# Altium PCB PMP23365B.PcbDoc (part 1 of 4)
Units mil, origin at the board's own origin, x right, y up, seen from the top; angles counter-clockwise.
Board outline 5450 x 2600 mil, 4 copper layers (Top Layer, Signal Layer 1, Signal Layer 2, Bottom Layer), stack 61.2 mil thick; 303 components, 149 nets, 783 pads, 285 vias.
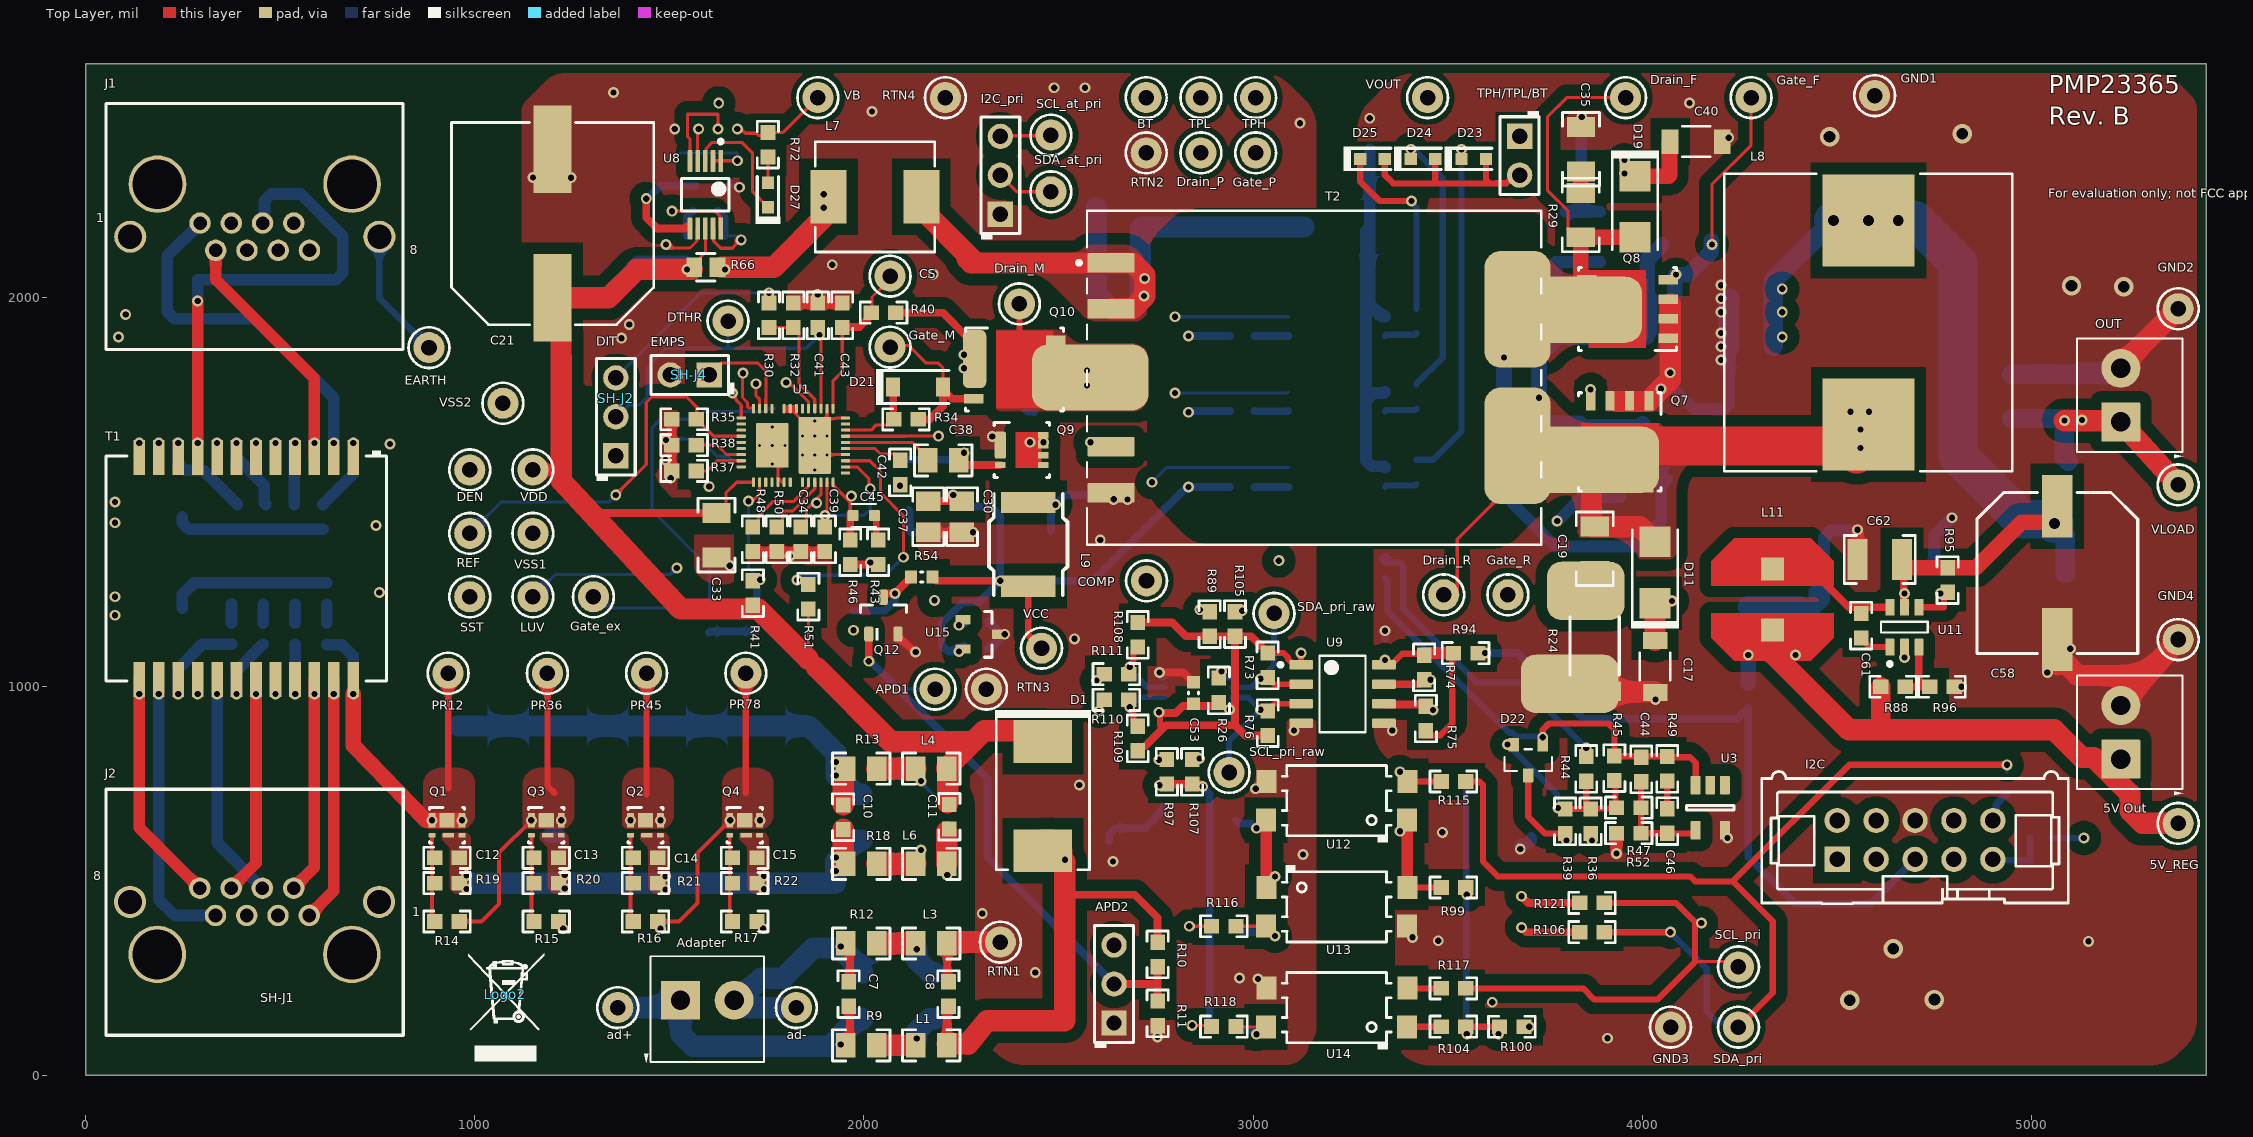
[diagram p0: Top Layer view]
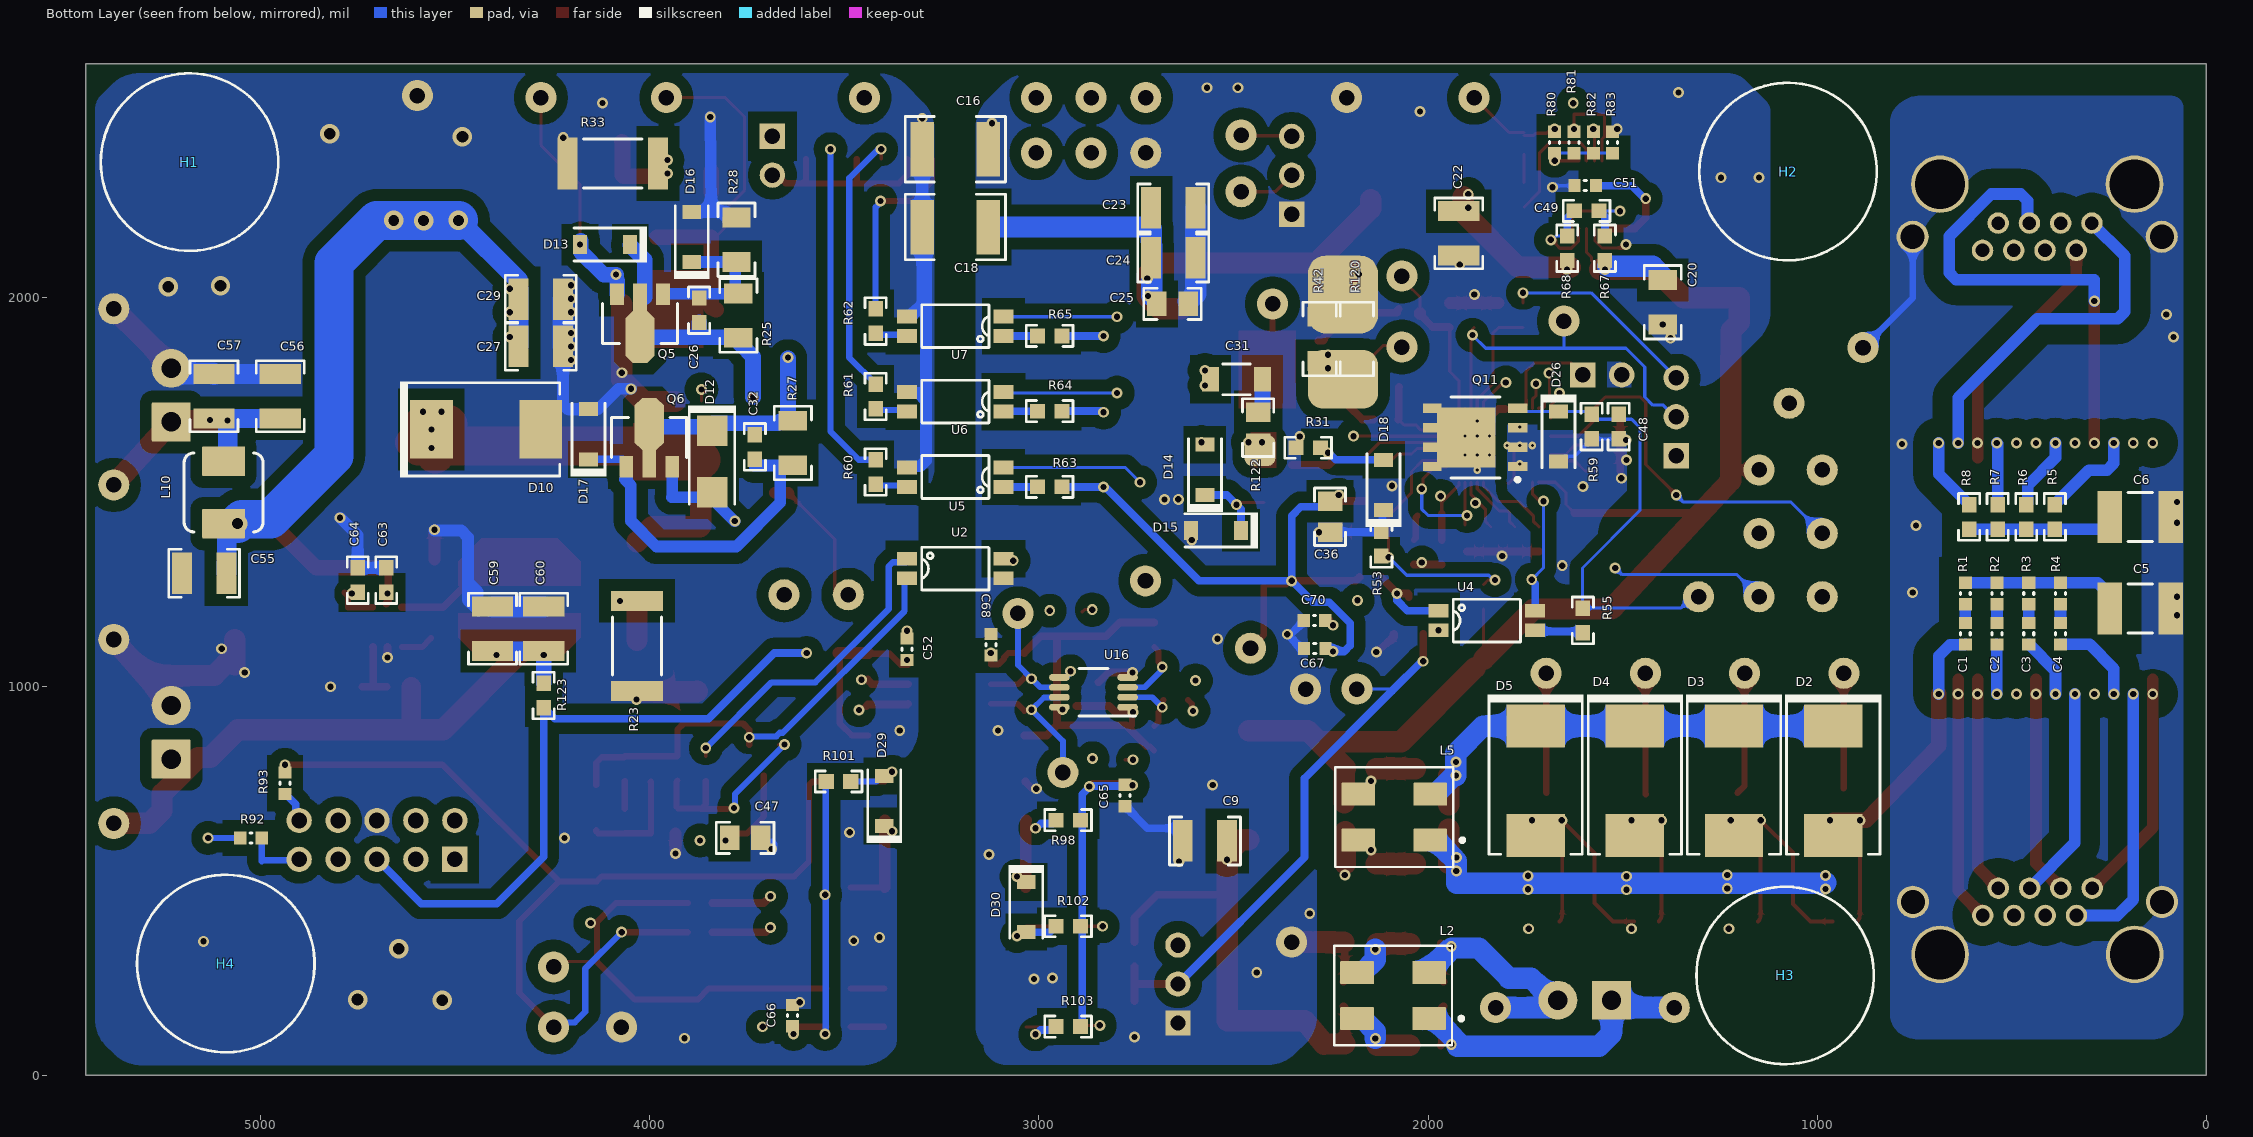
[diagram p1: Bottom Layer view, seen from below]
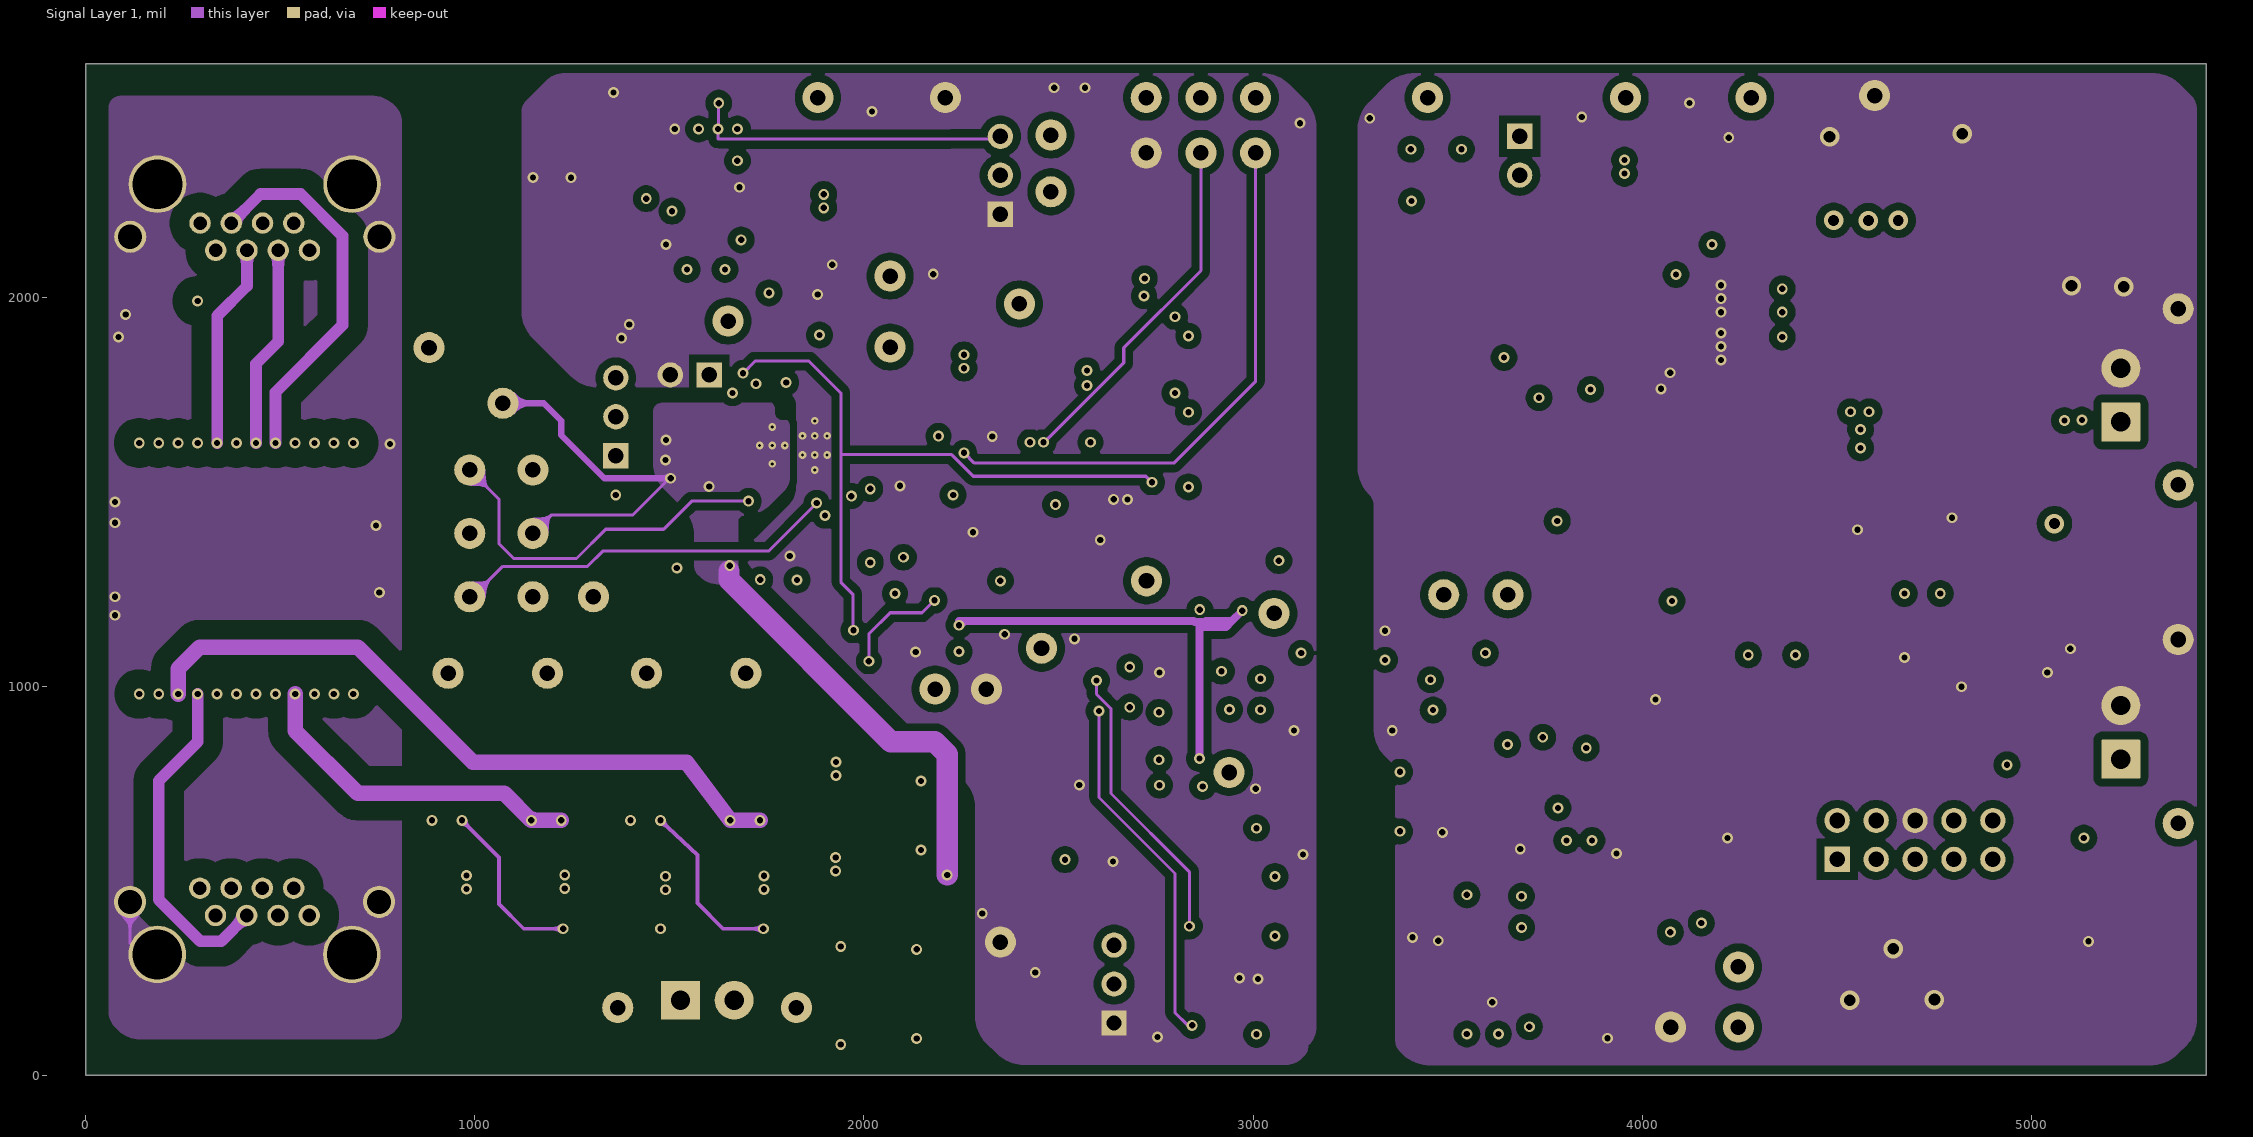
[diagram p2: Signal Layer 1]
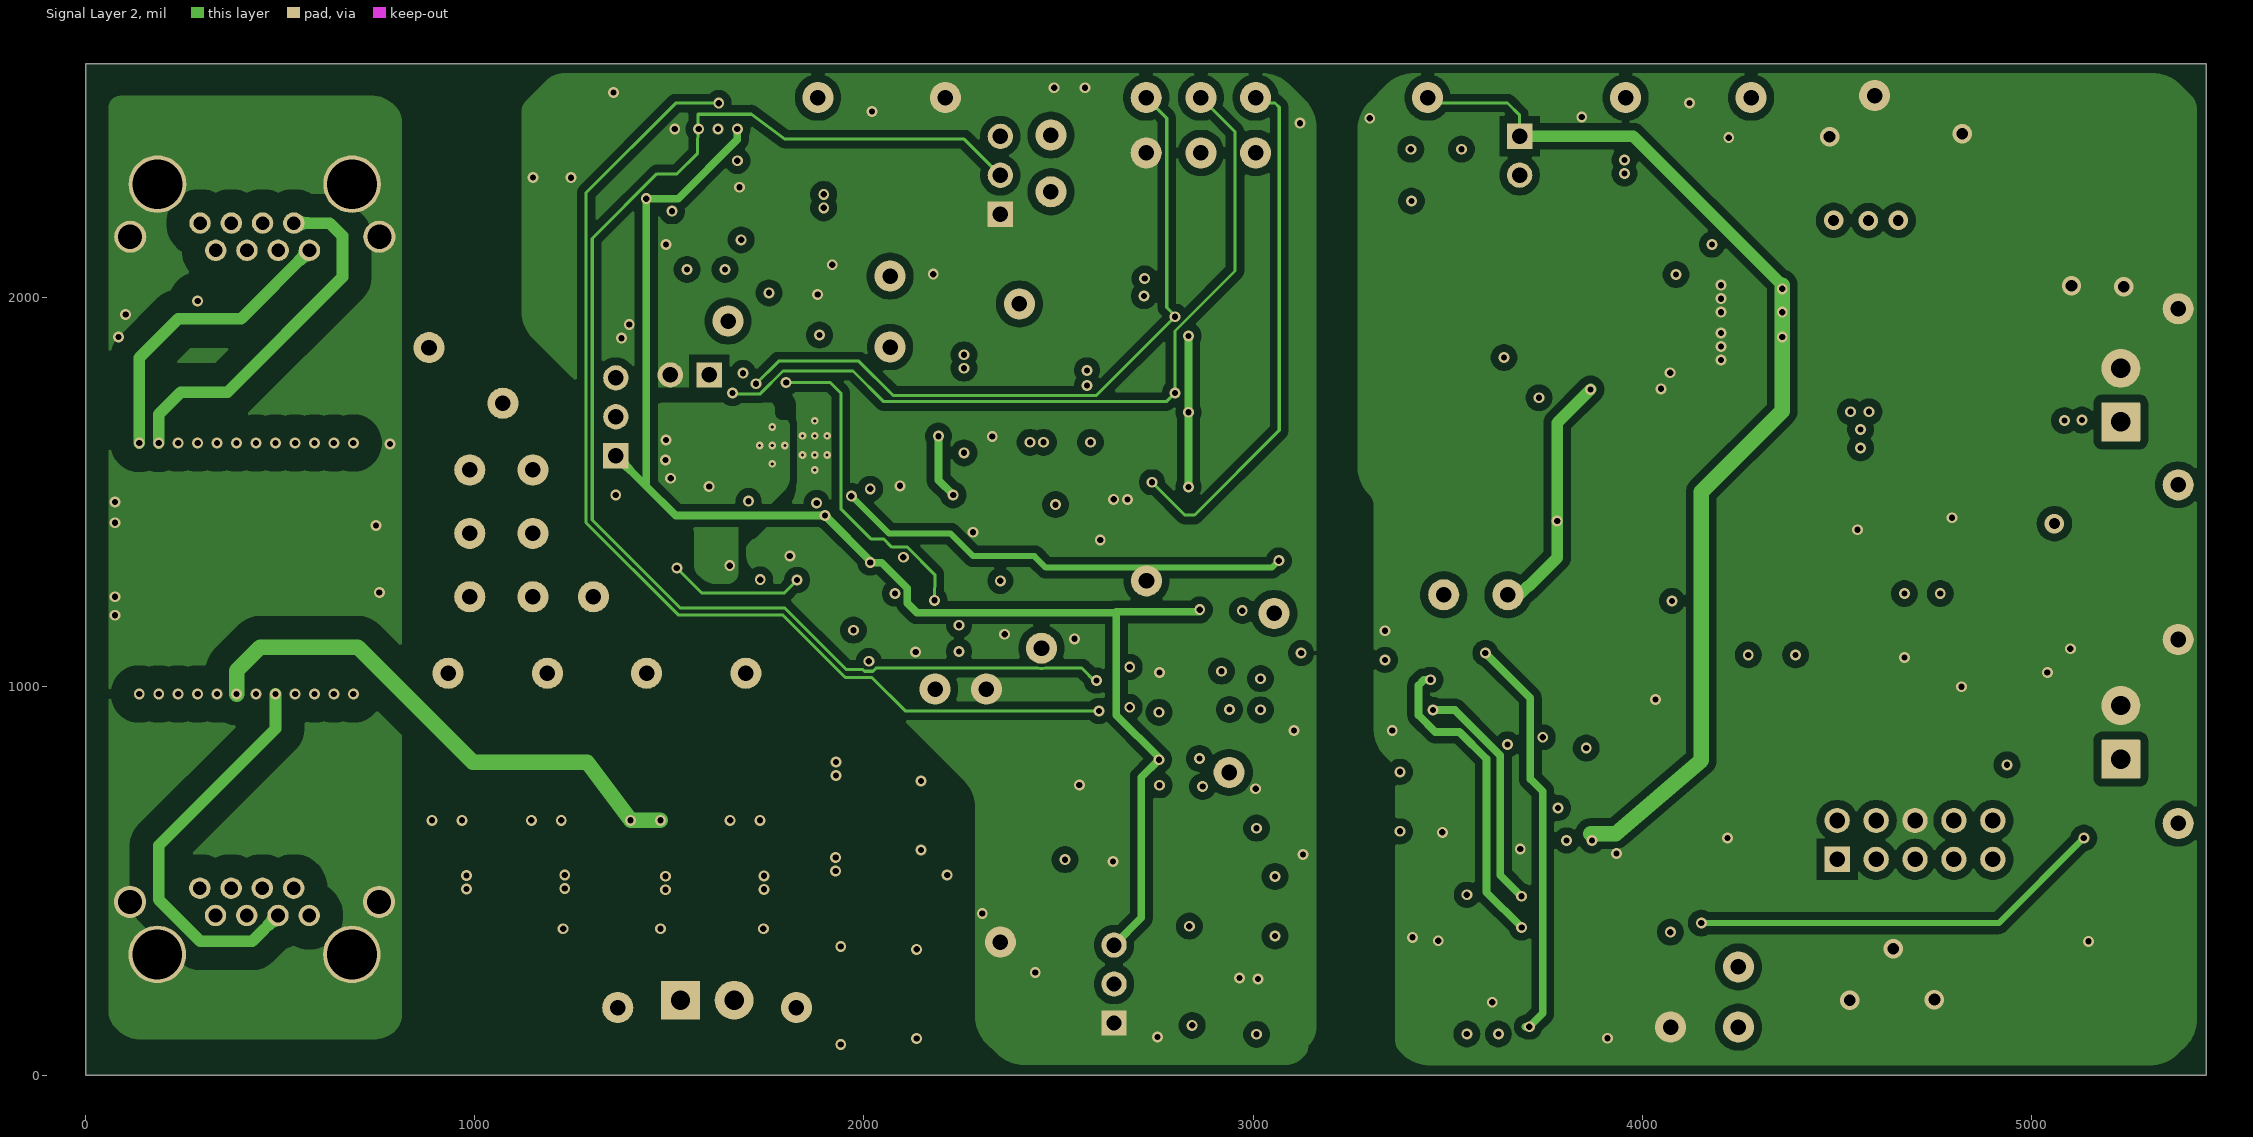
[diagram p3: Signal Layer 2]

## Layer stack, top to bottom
Top Solder: solder mask 0.4, Solder Resist, Dk 3.5
Top Layer: signal copper 2.8
Dielectric 1: prepreg 15, FR-4, Dk 4.8
Signal Layer 1: signal copper 2.8
Dielectric 2: core 20, FR-4, Dk 4.2
Signal Layer 2: signal copper 2.8
Dielectric 3: prepreg 15, FR-4, Dk 4.2
Bottom Layer: signal copper 2.8
Bottom Solder: solder mask 0.4, Solder Resist, Dk 3.5

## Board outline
0,0 5450,0 5450,2600 0,2600

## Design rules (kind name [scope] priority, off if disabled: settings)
AcuteAngle [All] p1: minimum=4.50000000000000E+0001 checktracksonly=FALSE
AssemblyTestPointUsage [All] p1: valid=2
BoardOutlineClearance BoardOutlineClearance_MountingHoles [OnCopper and InComponentClass('Mounting Holes')] p1: gap=39.37 ignorepadtopadclearanceinfootprint=FALSE
BoardOutlineClearance BoardOutlineClearance_Poly [OnCopper and IsPoly] p2: gap=25 ignorepadtopadclearanceinfootprint=FALSE
BoardOutlineClearance [OnCopper and Not InComponentClass('Logo') and not InComponentClass('FiducialMark') and not InRegion(1000,500,4000,800) and not InPoly] p3: gap=75 ignorepadtopadclearanceinfootprint=FALSE
Clearance Clearance_14 [InNamedPolygon('SIGNAL_LAYER_2_EARTH_P016')] p1: gap=60 ignorepadtopadclearanceinfootprint=FALSE
Clearance Clearance_13 [InNamedPolygon('SIGNAL_LAYER_1_EARTH_P014')] p2: gap=60 ignorepadtopadclearanceinfootprint=FALSE
Clearance Clearance_12 [InNamedPolygon('BOTTOM_LAYER_EARTH_P013')] p3: gap=60 ignorepadtopadclearanceinfootprint=FALSE
Clearance Clearance_11 [InNamedPolygon('SIGNAL_LAYER_2_EARTH_P012')] p4: gap=60 ignorepadtopadclearanceinfootprint=FALSE
Clearance Clearance_10 [InNamedPolygon('TOP_LAYER_EARTH_P015')] p5: gap=60 ignorepadtopadclearanceinfootprint=FALSE
Clearance Clearance_9 [InNamedPolygon('TOP_LAYER_EARTH_P015')] p6: gap=60 ignorepadtopadclearanceinfootprint=FALSE
Clearance Clearance_8 [InNamedPolygon('TOP_LAYER_EARTH_P015')] p7: gap=10 ignorepadtopadclearanceinfootprint=FALSE except(0: Arc-Hole Track-Hole SMDPad-Hole THPad-Hole Via-Hole Fill-Hole Poly-Hole Region-Hole Text-Hole)
Clearance "60 Mils_1" [InNamedPolygon('SIGNAL_LAYER_1_EARTH_P014')] p8: gap=10 ignorepadtopadclearanceinfootprint=FALSE except(0: Arc-Hole Track-Hole SMDPad-Hole THPad-Hole Via-Hole Fill-Hole Poly-Hole Region-Hole Text-Hole)
Clearance "60 Mils" [InNamedPolygon('SIGNAL_LAYER_2_EARTH_P012')] p9: gap=10 ignorepadtopadclearanceinfootprint=FALSE except(0: Arc-Hole Track-Hole SMDPad-Hole THPad-Hole Via-Hole Fill-Hole Poly-Hole Region-Hole Text-Hole)
Clearance Clearance_7 [InNamedPolygon('BOTTOM_LAYER_EARTH_P032')] p10: gap=10 ignorepadtopadclearanceinfootprint=FALSE except(0: Arc-Hole Track-Hole SMDPad-Hole THPad-Hole Via-Hole Fill-Hole Poly-Hole Region-Hole Text-Hole)
Clearance Clearance_6 [InNamedPolygon('TOP_LAYER_EARTH_P030')] p11: gap=10 ignorepadtopadclearanceinfootprint=FALSE except(0: Arc-Hole Track-Hole SMDPad-Hole THPad-Hole Via-Hole Fill-Hole Poly-Hole Region-Hole Text-Hole)
Clearance Clearance_5 [InNamedPolygon('BOTTOM_LAYER_EARTH_P032')] p12: gap=10 ignorepadtopadclearanceinfootprint=FALSE except(0: Arc-Hole Track-Hole SMDPad-Hole THPad-Hole Via-Hole Fill-Hole Poly-Hole Region-Hole Text-Hole)
Clearance Clearance_4 [InNamedPolygon('TOP_LAYER_EARTH_P030')] p13: gap=10 ignorepadtopadclearanceinfootprint=FALSE except(0: Arc-Hole Track-Hole SMDPad-Hole THPad-Hole Via-Hole Fill-Hole Poly-Hole Region-Hole Text-Hole)
Clearance Clearance_3 [InNamedPolygon('SIGNAL_LAYER_1_EARTH_P014')] p14: gap=10 ignorepadtopadclearanceinfootprint=FALSE except(0: Arc-Hole Track-Hole SMDPad-Hole THPad-Hole Via-Hole Fill-Hole Poly-Hole Region-Hole Text-Hole)
Clearance Clearance_2 [InNamedPolygon('SIGNAL_LAYER_2_EARTH_P012')] p15: gap=10 ignorepadtopadclearanceinfootprint=FALSE except(0: Arc-Hole Track-Hole SMDPad-Hole THPad-Hole Via-Hole Fill-Hole Poly-Hole Region-Hole Text-Hole)
Clearance Clearance_1 [InNamedPolygon('BOTTOM_LAYER_EARTH_P032')] p16: gap=10 ignorepadtopadclearanceinfootprint=FALSE except(0: Arc-Hole Track-Hole SMDPad-Hole THPad-Hole Via-Hole Fill-Hole Poly-Hole Region-Hole Text-Hole)
Clearance Clearance_Keepouts [((IsTrack Or IsArc) And Not InPoly) And IsFree and IsKeepOut vs ((IsTrack Or IsArc) And Not InPoly) And IsFree and IsKeepOut] p17: gap=0 ignorepadtopadclearanceinfootprint=FALSE
Clearance Clearance_Poly [InPolygon] p18: gap=10 ignorepadtopadclearanceinfootprint=TRUE
Clearance Clearance_FiducialMark [IsKeepOut and InComponentClass('FiducialMark') vs IsPad and InComponentClass('FiducialMark')] p19: gap=0 ignorepadtopadclearanceinfootprint=FALSE
Clearance [All] p20: gap=7.87 ignorepadtopadclearanceinfootprint=TRUE
ComponentClearance ComponentClearance_MountingHoles_FiducialMarks [InComponentClass('Mounting Holes') vs InComponentClass('FiducialMark')] p1 off: gap=50 collisioncheckmode=3 verticalgap=10 showdistances=FALSE
ComponentClearance ComponentClearance_Shunt [InComponentClass('Header') vs InComponentClass('Shunt')] p2 off: gap=0 collisioncheckmode=3 verticalgap=0 showdistances=FALSE
ComponentClearance ComponentClearance_Logo [InComponentClass('Logo')] p3 off: gap=50 collisioncheckmode=3 verticalgap=10 showdistances=FALSE
ComponentClearance ComponentClearance_ScrewToNut [(HasFootprint('NY PMS 440 0025 PH')) vs (HasFootprint('Keystone_1902C'))] p4 off: gap=5 collisioncheckmode=3 verticalgap=10 showdistances=FALSE
ComponentClearance ComponentClearance_MountingHoles [InComponentClass('Mounting Holes')] p5 off: gap=250 collisioncheckmode=3 verticalgap=100000 showdistances=FALSE
ComponentClearance ComponentClearance_SmallPassives [HasFootprint('0201*') or HasFootprint('0402*') or HasFootprint('0508') or HasFootprint('0603*') or HasFootprint('0612') or HasFootprint('0805*') or HasFootprint('0815*') or HasFootprint('0830*') or HasFootprint('1206*') or HasFootprint('1210*') or HasFootprint('1808*') or HasFootprint('1812*') or HasFootprint('1825*') or HasFootprint('2010*') or HasFootprint('2220*') or HasFootprint('2225*') or HasFootprint('2512*') or HasFootprint('2728*') or HasFootprint('3518*') vs HasFootprint('0201*') or HasFootprint('0402*') or HasFootprint('0508') or HasFootprint('0603*') or HasFootprint('0612') or HasFootprint('0805*') or HasFootprint('0815*') or HasFootprint('0830*') or HasFootprint('1206*') or HasFootprint('1210*') or HasFootprint('1808*') or HasFootprint('1812*') or HasFootprint('1825*') or HasFootprint('2010*') or HasFootprint('2220*') or HasFootprint('2225*') or HasFootprint('2512*') or HasFootprint('2728*') or HasFootprint('3518*')] p6 off: gap=14.96 collisioncheckmode=3 verticalgap=10 showdistances=FALSE
ComponentClearance ComponentClearance_THtoSMT [IsThruComponent vs IsSMTComponent] p7 off: gap=40 collisioncheckmode=3 verticalgap=30 showdistances=FALSE
ComponentClearance ComponentClearance_THtoTH [IsThruComponent vs IsThruComponent] p8 off: gap=30 collisioncheckmode=3 verticalgap=30 showdistances=FALSE
ComponentClearance [All] p9 off: gap=30 collisioncheckmode=3 verticalgap=10 showdistances=FALSE
DiffPairsRouting [All] p1: maxlimit=100 minlimit=10 mostfreqgap=10 toplayer_minwidth=15 toplayer_maxwidth=15 toplayer_prefwidth=15 midlayer1_minwidth=15 midlayer1_maxwidth=15 midlayer1_prefwidth=15 midlayer2_minwidth=15 midlayer2_maxwidth=15 midlayer2_prefwidth=15 bottomlayer_minwidth=15 bottomlayer_maxwidth=15 bottomlayer_prefwidth=15 maxuncoupledlength=1000
FabricationTestPointUsage TestPointUsage [All] p1: valid=2 allowmultiple=FALSE
FabricationTestpoint Testpoint [All] p1: side=3 testpointundercomponent=TRUE minsize=40 maxsize=100 preferedsize=60 minholesize=0 maxholesize=40 preferedholesize=32 testpointgrid=1 allowsidetop=TRUE allowsidebottom=TRUE usegrid=TRUE gridtolerance=0.01
FanoutControl Fanout_LCC [IsLCC] p1: bgadir=Out bgaviamode=Centered fanoutstyle=Auto fanoutdirection=Alternating viagrid=1 // Fanout_LCC (Default Rule)
FanoutControl Fanout_BGA [IsBGA] p2: bgadir=Out bgaviamode=Centered fanoutstyle=Auto fanoutdirection=Alternating viagrid=1 // Fanout_BGA (Default Rule)
FanoutControl Fanout_Default [All] p4: bgadir=Out bgaviamode=Centered fanoutstyle=Auto fanoutdirection=Alternating viagrid=1 // Fanout_Default (Default Rule)
FanoutControl Fanout_Small [(CompPinCount < 5)] p5: bgadir=Out bgaviamode=Centered fanoutstyle=Auto fanoutdirection=OutThenIn viagrid=1 // Fanout_Small (Default Rule)
HoleSize [All] p1: absolutevalues=TRUE maxlimit=251 minlimit=7.87 maxpercent=80.000 minpercent=20.000
MinimumAnnularRing MinimumAnnularRing_ThermalPadVias [IsVia and InAnyComponent] p1: minimumring=5.91
MinimumAnnularRing [All] p2: minimumring=7.87
MinimumSolderMaskSliver MinimumSolderMaskSliver_Logo [InComponentClass('Logo') vs InComponentClass('Logo')] p1: minsoldermaskwidth=0.7
MinimumSolderMaskSliver [All] p2: minsoldermaskwidth=3.94
PlaneConnect [All] p1: planeconnectstyle=Relief reliefexpansion=10 reliefentries=4 reliefconductorwidth=10 reliefairgap=10
PolygonConnect [All] p1: connectstyle=Direct reliefconductorwidth=10 reliefentries=4 polygonreliefangle="90 Angle" airgapwidth=10
RoutingVias ThermalPadVias [IsVia and InAnyComponent] p1: holewidth=7.87 width=19.68 viastyle="Through Hole" minholewidth=7.87 minwidth=19.68 maxholewidth=12.99 maxwidth=23.62
RoutingVias [All] p2: holewidth=16 width=34 viastyle="Through Hole" minholewidth=7.87 minwidth=26 maxholewidth=40 maxwidth=65
SilkToBoardRegionClearance [Not ((IsComment or IsDesignator) And (Hide <> 'False')) and not InRegion(1000,500,4000,800)] p1:
SilkToSilkClearance SilkToSilkClearance_Pb-FreeLogo [(HasFootprint('Pb-Free_Overlay_Medium') OR HasFootprint('Pb-Free_Overlay_Small')) vs (HasFootprint('Pb-Free_Overlay_Medium') OR HasFootprint('Pb-Free_Overlay_Small'))] p1: silktosilkclearance=0
SilkToSilkClearance [All] p2: silktosilkclearance=3.94
SilkToSolderMaskClearance SilkToComponentPadClearance [(IsPad or IsFill or IsRegion) and InAnycomponent] p1: minsilkscreentomaskgap=5 clearancetoexposedcopper=TRUE
SilkToSolderMaskClearance "Silk to Solder Mask Opening" [All] p2: minsilkscreentomaskgap=3.94 clearancetoexposedcopper=FALSE
SolderMaskExpansion [All] p1: expansion=1.97 istentingtop=FALSE
UnRoutedNet [All] p1: checkbadconnections=TRUE
Width [All] p1: maxlimit=100 minlimit=8 preferedwidth=15 checkconnectedcopper=TRUE
14 further rules are at their usual default settings.

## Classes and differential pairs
component class "TPS23730_ext FET+Tel_SH3": "5V Out" 5V_REG C49 C51 C52 C53 C55 C56 C57 C58 C59 C60 C61 C62 C63 C64 C65 C66 C67 C68 C70 D27 D29 D30 GND4 I2C I2C_pri J13 L10 L11 OUT R26 R66 R67 R68 R72 R73 R74 R75 R76 R80 R81 R82 R83 R88 R89 R92 R93 R94 R95 R96 R97 R98 R99 R100 R101 R102 R103 R104 R105 R106 R107 R108 R109 R110 R111 R115 R116 R117 R118 R121 R123 RTN4 SCL_at_pri SCL_pri SCL_pri_raw SDA_at_pri SDA_pri SDA_pri_raw U8 U9 U11 U12 U13 U14 U15 U16 VLOAD
component class Shunt: SH-J1 SH-J2 SH-J4
component class "TPS23730_ext FET+Tel_SH1": ad+ ad- Adapter APD1 APD2 C1 C2 C3 C4 C5 C6 C7 C8 C9 C10 C11 C12 C13 C14 C15 D1 D2 D3 D4 D5 EARTH H1 H2 H3 H4 J1 J2 L1 L2 L3 L4 L5 L6 Logo1 Logo2 PR12 PR36 PR45 PR78 Q1 Q2 Q3 Q4 R1 R2 R3 R4 R5 R6 R7 R8 R9 R10 R11 R12 R13 R14 R15 R16 R17 R18 R19 R20 R21 R22 SH-J1 SH-J2 SH-J4 T1
component class "TPS23730_ext FET+Tel_SH2": BT C16 C17 C18 C19 C20 C21 C22 C23 C24 C25 C26 C27 C29 C30 C31 C32 C33 C34 C35 C36 C37 C38 C39 C40 C41 C42 C43 C44 C45 C46 C47 C48 COMP CS D10 D11 D12 D13 D14 D15 D16 D17 D18 D19 D21 D22 D23 D24 D25 D26 DEN DIT Drain_F Drain_M Drain_P Drain_R DTHR EMPS Gate_ex Gate_F Gate_M Gate_P Gate_R GND1 GND2 GND3 L7 L8 L9 LUV Q5 Q6 Q7 Q8 Q9 Q10 Q11 Q12 R23 R24 R25 R27 R28 R29 R30 R31 R32 R33 R34 R35 R36 R37 R38 R39 R40 R41 R42 R43 R44 R45 R46 R47 R48 R49 R50 R51 R52 R53 R54 R55 R59 R60 R61 R62 R63 R64 R65 R120 R122 REF RTN1 RTN2 RTN3 SST T2 TPH TPH/TPL/BT TPL U1 U2 U3 U4 U5 U6 U7 VB VCC VDD VOUT VSS1 VSS2
component class Header: APD2 DIT EMPS I2C_pri TPH/TPL/BT

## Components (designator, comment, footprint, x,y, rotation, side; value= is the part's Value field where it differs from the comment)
"5V Out" "CMP-0074913-1" TERM_BLK_ED555-2DS 5230,812.5 r90 top
5V_REG "PG" Keystone5000 5377.5,647.5 r90 top
ad+ "5000" Keystone5000 1367.5,174.02 r90 top
ad- "5001" Keystone5001 1826.61,174.02 r90 top
Adapter "CMP-0074913-1" TERM_BLK_ED555-2DS 1528.73,193.06 r0 top
APD1 "5002" Keystone5002 2183.03,992.72 r90 top
APD2 "5-146278-3" TE_5-146278-3 2642.93,234.71 r90 top
BT "5002" Keystone5002 2725.48,2512.5 r0 top
C1 "Capacitor" 0603L 619.68,1135 r90 bottom value=0.01uF
C2 "Capacitor" 0603L 538.12,1135 r90 bottom value=0.01uF
C3 "Capacitor" 0603L 456.56,1135 r90 bottom value=0.01uF
C4 "Capacitor" 0603L 375,1135 r90 bottom value=0.01uF
C5 "GR443QR73D102KW01L" 1812 170,1200 r180 bottom value=1000pF
C6 "GR443QR73D102KW01L" 1812 170,1435 r180 bottom value=1000pF
C7 "C1608X7R2A102K080AA" 0603 1960.75,208.89 r90 top value=1000pF
C8 "C1608X7R2A102K080AA" 0603 2217.41,208.88 r90 top value=1000pF
C9 "Capacitor" 1210_270 2573.44,602.45 r180 bottom value=2.2uF
C10 "C1608X7R2A102K080AA" 0603 1946.53,663.47 r270 top value=1000pF
C11 "C1608X7R2A102K080AA" 0603 2219.83,664.57 r270 top value=1000pF
C12 "GRM1885C1H331JA01D" 0603 928.81,559.04 r0 top value=330pF
C13 "GRM1885C1H331JA01D" 0603 1183.81,559.04 r0 top value=330pF
C14 "GRM1885C1H331JA01D" 0603 1438.81,559.04 r0 top value=330pF
C15 "GRM1885C1H331JA01D" 0603 1693.81,559.04 r0 top value=330pF
C16 "C4532X7R3D222K130KA" 1812_HV 3215,2380 r180 bottom value=2200pF
C17 "GRM31CR72E473KW03L" 1206_180 4033.09,1050.9 r90 top value=0.047uF
C18 "C4532X7R3D222K130KA" 1812_HV 3215,2180 r180 bottom value=2200pF
C19 "VJ1206Y471KBEAT4X" 1206 3878.09,1353.11 r90 top value=470pF
C20 "GRM319R72A104KA01D" 1206 1397.04,1986.88 r270 bottom value=0.1uF
C21 "EMVA101ATR680MKE0S" CAPSMT_62_KE0 1200,2189.06 r90 top value=68uF
C22 "GRM32ER72A225KA35L" 1210_270 1921.09,2163.64 r270 bottom value=2.2uF
C23 "GRM32ER72A225KA35L" 1210_270 2654.69,2229.15 r180 bottom value=2.2uF
C24 "GRM32ER72A225KA35L" 1210_270 2654.69,2100.65 r180 bottom value=2.2uF
C25 "GRM21BR72A104KAC4L" 0805_HV 2656.93,1982.38 r180 bottom value=0.1uF
C26 "GCM1885C2A101JA16D" 0603 3873.2,1966.2 r270 bottom value=100pF
C27 "GRM32ER61H106KA12L" 1210_270 4280.33,1873.69 r180 bottom value=10uF
C29 "GRM32ER61H106KA12L" 1210_270 4280.33,1994.54 r180 bottom value=10uF
C30 "GRM21BR71E105KA99L" 0805_HV 2252.1,1435.67 r270 top value=1uF
C31 "GRM31CR72E473KW03L" 1206_180 2492.54,1788.74 r180 bottom value=0.047uF
C32 "GCM1885C2A101JA16D" 0603 3730,1615 r90 bottom value=100pF
C33 "GRM319R72A104KA01D" 1206 1621.27,1388.26 r270 top value=0.1uF
C34 "GRM188R71H473KA61D" 0603 1838.31,1377.5 r90 top value=0.047uF
C35 "VJ1206Y221KXEAT5Z" 1206 3842.66,2380 r270 top value=220pF
C36 "C2012X7R1V475K125AC" 0805_HV 2252.1,1435.51 r270 bottom value=4.7uF
C37 "GCM21BR71H104KA37K" 0805_HV 2165.49,1435.67 r270 top value=0.1uF
C38 "C2012X5R1H224K125AA" 0805_HV 2203.87,1580.23 r180 top value=0.22uF
C39 "CGA3E2X7R1E104K080AA" 0603 1900,1377.5 r90 top value=0.1uF
C40 "GRM31CR72E473KW03L" 1206_180 4138.89,2399.68 r180 top value=0.047uF
C41 "C0603C222K5RAC" 0603 1881.78,1953.18 r90 top value=2200pF
C42 "CGA3E2X7R1E104K080AA" 0603 2093.17,1549.46 r90 top value=0.1uF
C43 "GRM1885C1H470JA01D" 0603 1944.54,1953.18 r90 top value=47pF
C44 "GCM1885C2A101JA16D" 0603 3997.62,786.24 r90 top value=100pF
C45 "C1608X8R1E683M080AA" FP-C1608X8R1E683M080AA_0603-MFG 1999.76,1438.52 r0 top value=68nF
C46 "C0603X103K5RACTU" 0603 4064.55,653.37 r90 top value=0.01uF
C47 "C2012X7R1H105K125AB" 0805_HV 3755.16,610.17 r180 bottom value=1uF
C48 "GRM188R71H473KA61D" 0603 1510.38,1667.18 r270 bottom value=0.047uF
C49 "885012206095" 0603 1592.61,2221.48 r0 bottom value=0.1uF
C51 "GRJ188R71E105KE11D" 0603L 1596.17,2286.23 r0 bottom value=1uF
C52 "GRJ188R71E105KE11D" 0603L 3339.02,1095.23 r90 bottom value=1uF
C53 "GRJ188R71E105KE11D" 0603L 2847.53,982.56 r90 top value=1uF
C55 "GRM32ER61H106KA12L" 1210_270 5145.45,1290 r0 bottom value=10uF
C56 "GRM32ER61H106KA12L" 1210_270 4949.52,1745.1 r90 bottom value=10uF
C57 "GRM32ER61H106KA12L" 1210_270 5120,1745.1 r90 bottom value=10uF
C58 "EEH-ZC1H101P" Panasonic_G 5066.85,1291.26 r270 top value=100uF
C59 "GRM32ER71E226KE15L" 1210_270 4404.31,1147.46 r270 bottom value=22uF
C60 "GRM32ER71E226KE15L" 1210_270 4272.74,1147.46 r270 bottom value=22uF
C61 "885012206095" 0603 4562.71,1155.59 r90 top value=0.1uF
C62 "GRM32ER61H106KA12L" 1210_270 4610.55,1325.79 r180 top value=10uF
C63 "UMK107AB7105KA-T" 0603 4677.31,1272.61 r90 bottom value=1uF
C64 "UMK107AB7105KA-T" 0603 4750.52,1272.61 r90 bottom value=1uF
C65 "GRJ188R71E105KE11D" 0603L 2778.7,718.98 r270 bottom value=1uF
C66 "GRJ188R71E105KE11D" 0603L 3633.5,153.54 r90 bottom value=1uF
C67 "GRJ188R71E105KE11D" 0603L 2291.57,1097.09 r0 bottom value=1uF
C68 "GRJ188R71E105KE11D" 0603L 3123.7,1106.74 r90 bottom value=1uF
C70 "GRJ188R71E105KE11D" 0603L 2292,1168.44 r0 bottom value=1uF
COMP "5002" Keystone5002 2726.35,1270.8 r90 top
CS "5002" Keystone5002 2067.44,2053.81 r90 top
D1 "B3100-13-F" SMC 2460,717.5 r270 top value=100V
D2 "VS-30BQ100TRPBF" SMC 958.81,757.24 r270 bottom value=100V
D3 "VS-30BQ100TRPBF" SMC 1213.81,757.24 r270 bottom value=100V
D4 "VS-30BQ100TRPBF" SMC 1468.81,757.24 r270 bottom value=100V
D5 "VS-30BQ100TRPBF" SMC 1723.81,757.24 r270 bottom value=100V
D10 "SMCJ150A-TP" SMC 4420.82,1660 r180 bottom value=150V
D11 "ES1C-13-F" SMA 4033.09,1292.1 r90 top value=150V
D12 "ES1C-13-F" SMA 3840,1577.5 r270 bottom value=150V
D13 "RF081M2STR" SOD-123 4115,2135 r0 bottom value=200V
D14 "MMSD914T1G" SOD-123 2573.44,1556.16 r90 bottom value=100V
D15 "MMSD914T1G" SOD-123 2545,1400.36 r0 bottom value=100V
D16 "MMSZ5242B-7-F" SOD-123 3892.14,2154.68 r90 bottom value=12V
D17 "MMSZ5242B-7-F" SOD-123 4157.5,1647.5 r90 bottom value=12V
D18 "MMSD914T1G" SOD-123 2114.59,1517.4 r90 bottom value=100V
D19 "ES1C-13-F" SMA 3981.68,2232.1 r270 top value=150V
D21 "MMSD914T1G" SOD-123 2138.74,1768.83 r0 top value=100V
D22 "BAS70-04-E3-18" FP-BAS70-04-E3-18_SOT23-3-MFG 3707.12,810.21 r270 top
D23 "150060YS75000" WL-SMCW_YELLOW 3567.05,2354.89 r0 top value=Yellow
D24 "150060YS75000" WL-SMCW_YELLOW 3436.99,2354.89 r0 top value=Yellow
D25 "150060YS75000" WL-SMCW_YELLOW 3306.93,2354.9 r0 top value=Yellow
D26 "MMSZ5242B-7-F" SOD-123 1664.94,1641.4 r270 bottom value=12V
D27 "150060YS75000" WL-SMCW_YELLOW 1753.54,2262.61 r90 top value=Yellow
D29 "B0520LW-7-F" SOD-123 3397.5,705 r90 bottom value=20V
D30 "B0520LW-7-F" SOD-123 3032.5,432.5 r270 bottom value=20V
DEN "5002" Keystone5002 987.3,1555.77 r90 top
DIT "5-146278-3" TE_5-146278-3 1362.5,1692.44 r90 top
Drain_F "5003" Keystone5003 3957.5,2512.5 r90 top
Drain_M "5003" Keystone5003 2399.67,1982.38 r90 top
Drain_P "5003" Keystone5003 2866.17,2370.57 r180 top
Drain_R "5003" Keystone5003 3490,1235 r90 top
DTHR "5002" Keystone5002 1650.93,1938.33 r90 top
EARTH "5001" Keystone5001 882.5,1870 r90 top
EMPS "5-146278-2" TE_5-146278-2 1552.5,1800 r180 top
Gate_ex "5003" Keystone5003 1304.91,1229.93 r90 top
Gate_F "5003" Keystone5003 4280,2512.5 r90 top
Gate_M "5003" Keystone5003 2067.44,1871.46 r90 top
Gate_P "5003" Keystone5003 3006.85,2370.57 r180 top
Gate_R "5003" Keystone5003 3655,1235 r90 top
GND1 "5001" Keystone5001 4597.5,2517.79 r90 top
GND2 "5001" Keystone5001 5377.5,1970 r90 top
GND3 "5001" Keystone5001 4072.94,123.89 r180 top
GND4 "GND" Keystone5001 5377.5,1120 r90 top
H1 "SJ-5303 (CLEAR)" Bumpon_SJ5003Transparent 5182.99,2346.87 r90 bottom
H2 "SJ-5303 (CLEAR)" Bumpon_SJ5003Transparent 1075,2322.5 r180 bottom
H3 "SJ-5303 (CLEAR)" Bumpon_SJ5003Transparent 1082.48,256.65 r180 bottom
H4 "SJ-5303 (CLEAR)" Bumpon_SJ5003Transparent 5089.6,287.28 r180 bottom
I2C "N2510-6002-RB" CONN_2510-6002 4701.24,605 r0 top
I2C_pri "5-146278-3" TE_5-146278-3 2350.71,2313.07 r90 top
J1 "1-406541-1" TEC_1-406541-1 434.37,2182.99 r180 top
J2 "1-406541-1" TEC_1-406541-1 434.61,417.99 r0 top
L1 "74279220181" 0805_HV 2173.09,76.99 r0 top value="180 ohm"
L2 "CM7060P701R-10" FP-CM7060P701R-10_SMT_CMC_7MM0_6MM0-MFG 2090,205 r0 bottom
L3 "74279220181" 0805_HV 2173.09,338.88 r0 top value="180 ohm"
L4 "74279220181" 0805_HV 2173.09,788.36 r0 top value="180 ohm"
L5 "CM7060P701R-10" FP-CM7060P701R-10_SMT_CMC_7MM0_6MM0-MFG 2087.35,663.47 r0 bottom
L6 "74279220181" 0805_HV 2173.09,543.47 r0 top value="180 ohm"
L7 "PIMB065T-4R7" IND_PIMB065T 2028.37,2257.5 r0 top value=4.7uH
L8 "74435574700" WE-HCB_1890 4581.41,1934.7 r90 top value=47uH
L9 "DO1608C-105MLB" DO1608C 2422.41,1364.65 r90 top value=1mH
L10 "IHLP2020CZER1R0M11" IHLP-2020CZ 5095.25,1497.95 r90 bottom value=1uH
L11 "1273AS-H-150M=P3" DEM8030C 4334.46,1222.81 r270 top value=15uH
Logo1 "FCC disclaimer" FCC_disclaimer 830.97,3503.25 r0 top
Logo2 "WEEE logo" WEEE_Minimum 1078.81,208.89 r0 top
LUV "5002" Keystone5002 1149.36,1229.93 r90 top
OUT "ED555/2DS" TERM_BLK_ED555-2DS 5230,1679.05 r90 top
PR12 "5000" Keystone5000 931.66,1033.35 r90 top
PR36 "5001" Keystone5001 1186.66,1033.35 r90 top
PR45 "5002" Keystone5002 1441.66,1033.35 r90 top
PR78 "5003" Keystone5003 1696.66,1033.35 r90 top
Q1 "CSD19538Q2" DQK0006C 928.81,642.54 r0 top value=100V
Q2 "CSD19538Q2" DQK0006C 1438.81,642.54 r0 top value=100V
Q3 "CSD19538Q2" DQK0006C 1183.81,642.54 r0 top value=100V
Q4 "CSD19538Q2" DQK0006C 1693.81,642.54 r0 top value=100V
Q5 "FCX495TA" SOT-89-3 4025,1932.5 r270 bottom value="150 V"
Q6 "FCX495TA" SOT-89-3 4001.67,1638.49 r90 bottom value="150 V"
Q7 "FDMS86200" TRANS_Fairchild_PQFN08A 3942.57,1628.21 r270 top value=150V
Q8 "FDMS86200" TRANS_Fairchild_PQFN08A 3962.46,1969.54 r180 top value=150V
Q9 "FDMC2523P" MLP08S 2405.83,1606.81 r0 top value=-150V
Q10 "FDMS86250" TRANS_Fairchild_PQFN08A 2387.42,1813.74 r0 top value=150V
Q11 "FDMS86105" PowerPAK_SO-8_NoVias 1879.75,1639.44 r0 bottom value=100V
Q12 "2N7002-7-F" SOT-23 2049.94,1181.38 r90 top value=60V
R1 "Resistor" 0603L 619.68,1238.02 r270 bottom value=75.0
R2 "Resistor" 0603L 538.12,1238.02 r270 bottom value=75.0
R3 "Resistor" 0603L 456.56,1238.02 r270 bottom value=75.0
R4 "Resistor" 0603L 375,1238.02 r270 bottom value=75.0
R5 "RC0603FR-0775RL" 0603 389.39,1435 r270 bottom value=75.0
R6 "RC0603FR-0775RL" 0603 462.92,1435 r270 bottom value=75.0
R7 "RC0603FR-0775RL" 0603 536.46,1435 r270 bottom value=75.0
R8 "RC0603FR-0775RL" 0603 610,1435 r270 bottom value=75.0
R9 "MCR10EZPJ000" 0805_HV 1993.33,76.99 r0 top value=0
R10 "CRCW0603100KFKEA" 0603 2754.9,310.93 r90 top value=100k
R11 "CRCW060310K0FKEA" 0603 2754.9,159.37 r90 top value=10.0k
R12 "MCR10EZPJ000" 0805_HV 1993.33,338.88 r0 top value=0
R13 "MCR10EZPJ000" 0805_HV 1993.33,788.36 r0 top value=0
R14 "CMP-0022138-4" 0603 928.81,395.34 r0 top value=1.00Meg
R15 "CMP-0022138-4" 0603 1183.81,395.34 r0 top value=1.00Meg
R16 "CMP-0022138-4" 0603 1438.81,395.34 r0 top value=1.00Meg
R17 "CMP-0022138-4" 0603 1693.81,395.34 r0 top value=1.00Meg
R18 "MCR10EZPJ000" 0805_HV 1993.33,543.47 r0 top value=0
R19 "CMP-0022224-4" 0603 928.81,494.04 r180 top value=232k
R20 "CMP-0022224-4" 0603 1183.81,494.04 r180 top value=232k
R21 "CMP-0022224-4" 0603 1438.81,494.04 r180 top value=232k
R22 "CMP-0022224-4" 0603 1693.81,494.04 r180 top value=232k
R23 "CRCW251233K0JNEG" 2512 4033.09,1103.36 r270 bottom value=33k
R24 "CRCW251251R0JNEG" 2512 3878.09,1103.11 r270 top value=51
R25 "CRCW120610K0JNEA" 1206 3772.5,1952.5 r270 bottom value=10k
R26 "M55342K12B10E0T" 0603 2912.21,989.47 r270 top value=10.0k
R27 "CRCW12064K30JNEA" 1206 3632.5,1625 r90 bottom value=4.3k
R28 "CRCW120620K0FKEA" 1206 3777.14,2147.3 r270 bottom value=20.0k
R29 "CRCW120633R0JNEA" 1206 3842,2210.73 r90 top value=33
R30 "RC0603FR-07237KL" 0603 1756.18,1953.18 r270 top value=237k
R31 "CRCW060310K0FKEA" 0603 2308.19,1612.86 r180 bottom value=10.0k
R32 "CRCW060360K4FKEA" 0603 1818.95,1953.18 r270 top value=60.4k
R33 "CRCW251210K0JNEG" 2512 4095.43,2343.69 r0 bottom value=10k
R34 "CRCW060310R0JNEA" 0603 2108.16,1685.7 r0 top value=10
R35 "CRCW060349K9FKEA" 0603 1538,1686.09 r0 top value=49.9k
R36 "CRCW060310R0JNEA" 0603 3867.71,652.92 r270 top value=10
R37 "RC0603FR-0731R6L" 0603 1538,1553.11 r0 top value=31.6
R38 "RC0603FR-0745R3L" 0603 1538,1619.6 r0 top value=45.3
R39 "CRCW0603100KJNEAC" 0603 3802.29,652.92 r90 top value=100k
R40 "RC0603FR-072KL" 0603 2050.58,1959.99 r0 top value=2.00k
R41 "RC0603FR-0727K4L" 0603 1714.94,1239.34 r90 top value=27.4k
R42 "ERJ-8CWFR050V" 1206 2273.74,1892.37 r270 bottom value=0.05
R43 "RC0603FR-071K47L" 0603 2036.64,1344.25 r270 top value=1.47k
R44 "CRCW06034K99FKEA" 0603 3856.25,787.67 r270 top value=4.99k
R45 "CRCW06034K99FKEA" 0603 3928.73,789.35 r270 top value=4.99k
R46 "CRCW06032K00FKEA" 0603 1964.87,1344.25 r270 top value=2.00k
R47 "CRCW060340K2FKEA" 0603 3965.59,687.81 r0 top value=40.2k
R48 "CRCW060364K9FKEA" 0603 1714.88,1377.5 r270 top value=64.9k
R49 "CRCW06031K00FKEA" 0603 4064.55,787.76 r270 top value=1.00k
R50 "CRCW0603499KFKEA" 0603 1776.63,1377.5 r90 top value=499k
R51 "CRCW0603110KFKEA" 0603 1857.5,1230 r270 top value=110k
R52 "RC0603FR-074K64L" 0603 3965.59,622.32 r0 top value=4.64k
R53 "CRCW060310K0FKEA" 0603 2120.04,1365.91 r270 bottom value=10.0k
R54 "CRCW060310K0FKEA" 0603L 2148.58,1280.64 r0 top value=10.0k
R55 "CRCW060364K9FKEA" 0603 1602.3,1169.25 r90 bottom value=64.9k
R59 "CRCW0603100KFKEA" 0603 1579.6,1667.18 r90 bottom value=100k
R60 "CRCW060320K0JNEA" 0603 3420,1550.55 r90 bottom value=20k
R61 "CRCW060320K0JNEA" 0603 3420,1744.44 r90 bottom value=20k
R62 "CRCW060320K0JNEA" 0603 3420,1938.33 r90 bottom value=20k
R63 "CRCW060320K0JNEA" 0603 2972.4,1512.22 r180 bottom value=20k
R64 "CRCW060320K0JNEA" 0603 2972.4,1706.94 r180 bottom value=20k
R65 "CRCW060320K0JNEA" 0603 2972.4,1900 r180 bottom value=20k
R66 "WSL0805R0100FEA18" WSLHP0805 1594.01,2076.48 r0 top value=0.01
R67 "RC0603FR-0720RL" 0603 1545.74,2125.43 r270 bottom value=20.0
R68 "RC0603FR-0720RL" 0603 1642.61,2125.43 r270 bottom value=20.0
R72 "M55342K12B10E0T" 0603 1753.62,2391.65 r90 top value=10.0k
R73 "M55342K12B10E0T" 0603 3037.76,1053.74 r90 top value=10.0k
R74 "M55342K12B10E0T" 0603 3439.9,1048.49 r270 top value=10.0k
R75 "M55342K12B10E0T" 0603 3444.16,917.11 r90 top value=10.0k
R76 "M55342K12B10E0T" 0603 3037.76,905 r270 top value=10.0k
R80 "CRCW0603100RFKEA" 0603L 1674.88,2397.45 r90 bottom value=100
R81 "CRCW0603100RFKEA" 0603L 1625.19,2397.45 r90 bottom value=100
R82 "CRCW0603100RFKEA" 0603L 1575.5,2397.45 r90 bottom value=100
R83 "CRCW0603100RFKEA" 0603L 1525.8,2397.45 r90 bottom value=100
R88 "CRCW0603100KFKEA" 0603 4645,998.7 r180 top value=100k
R89 "ERJ-3GEY0R00V" 0603 2888.7,1159.73 r90 top value=0
R92 "CRCW0603100RFKEA" 0603L 5024.94,610 r0 bottom value=100
R93 "CRCW0603100RFKEA" 0603L 4937.5,750.81 r270 bottom value=100
R94 "ERJ-3GEY0R00V" 0603 3546.5,1085.24 r0 top value=0
R95 "CRCW060320K0JNEA" 0603 4784.79,1272.61 r90 top value=20k
R96 "CRCW060319K6FKEA" 0603 4770.57,998.7 r180 top value=19.6k
R97 "ERJ-3GEY0R00V" 0603 2778.7,780 r90 top value=0
R98 "CRCW06031K00FKEA" 0603 2925,655.72 r0 bottom value=1.00k
R99 "CRCW06031K00FKEA" 0603 3515,482.69 r0 top value=1.00k
R100 "ERJ-3GEY0R00V" 0603 3665,125 r180 top value=0
R101 "M55342K12B10E0T" 0603 3515,755.19 r0 bottom value=10.0k
R102 "RC0603FR-0715KL" 0603 2925,383.22 r0 bottom value=15.0k
R103 "CRCW06034K99FKEAC" 0603 2925,125.54 r0 bottom value=4.99k
R104 "CRCW06031K00FKEA" 0603 3515,125 r0 top value=1.00k
R105 "ERJ-3GEY0R00V" 0603 2953.7,1159.73 r270 top value=0
R106 "ERJ-3GEY0R00V" 0603 3871.09,368.03 r0 top value=0
R107 "ERJ-3GEY0R00V" 0603 2843.7,780 r270 top value=0
R108 "M55342K12B10E0T" 0603 2703.86,1132.2 r90 top value=10.0k
R109 "M55342K12B10E0T" 0603 2703.8,866 r270 top value=10.0k
R110 "ERJ-3GEY0R00V" 0603 2648.81,964.75 r180 top value=0
R111 "ERJ-3GEY0R00V" 0603 2648.81,1030.95 r0 top value=0
R115 "ERJ-3GEY0R00V" 0603 3515,755.19 r180 top value=0
R116 "ERJ-3GEY0R00V" 0603 2925,383.22 r180 top value=0
R117 "ERJ-3GEY0R00V" 0603 3515,223.35 r0 top value=0
R118 "ERJ-3GEY0R00V" 0603 2925,125.54 r180 top value=0
R120 "CRM1206-FX-R100ELF" 1206 2188.12,1892.39 r270 bottom value=0.1
R121 "ERJ-3GEY0R00V" 0603 3871.09,443.01 r0 top value=0
R122 "MCR10EZPJ000" 0805_HV 2436.99,1664.44 r90 bottom value=0
R123 "ERJ-3GEY0R00V" 0603 4272.74,976.14 r90 bottom value=0
REF "5002" Keystone5002 987.3,1392.85 r90 top
RTN1 "5001" Keystone5001 2350.71,342.42 r90 top
RTN2 "5001" Keystone5001 2725.48,2370.57 r180 top
RTN3 "5001" Keystone5001 2315,992.5 r90 top
RTN4 "GND" Keystone5001 2209.32,2512.5 r90 top
SCL_at_pri "5002" Keystone5002 2480.53,2416.15 r90 top
SCL_pri "5002" Keystone5002 4247.5,278.74 r90 top
SCL_pri_raw "5002" Keystone5002 2938.71,778.33 r90 top
SDA_at_pri "5002" Keystone5002 2480.53,2270.59 r90 top
SDA_pri "5002" Keystone5002 4247.5,123.89 r90 top
SDA_pri_raw "5002" Keystone5002 3054.02,1187.14 r90 top
SH-J1 "60900213421" Wurth_60900213421 3685.12,2363.38 r90 top
SH-J2 "60900213421" Wurth_60900213421 1362.5,1739.89 r90 top
SH-J4 "60900213421" Wurth_60900213421 1550,1800 r180 top
SST "5002" Keystone5002 987.3,1229.93 r90 top
T1 "7490220122" Wurth_7490220122 412.95,1302.46 r270 top value=350uH
T2 "750320237" FP-750320237_SMT12_29MM65_21MM8-MFG 3157.1,1792.38 r0 top
TPH "5002" Keystone5002 3006.85,2512.5 r90 top
TPH/TPL/BT "5-146278-2" TE_5-146278-2 3685.12,2363.38 r270 top
TPL "5002" Keystone5002 2866.17,2512.5 r90 top
U1 "TPS23730RMT" RMT0045A 1818.73,1618.77 r270 top
U2 "TCMT1107" SOP-4 3215,1302.5 r180 bottom
U3 "TL431IDBVR" DBV0005A_M 4175,687.81 r270 top
U4 "TCMT1104" SOP-4 1848.96,1168.98 r180 bottom
U5 "TCMT1104" SOP-4 3215,1537.22 r0 bottom
U6 "TCMT1104" SOP-4 3215,1731.11 r0 bottom
U7 "TCMT1104" SOP-4 3215,1925 r0 bottom
U8 "INA237AQDGSRQ1" DGS0010A-MFG 1592.61,2262.93 r270 top
U9 "ISO1640BDR" D0008A-MFG 3230,980 r0 top
U11 "LMR54410DBVR" DBV0006A-MFG 4673.99,1151.73 r90 top
U12 "FOD817DS" N04C 3215,705.72 r180 top
U13 "FOD817DS" N04C 3215,433.22 r0 top
U14 "FOD817DS" N04C 3215,173.89 r180 top
U15 "TLV76050DBZR" DBZ0003A_N 2302,1133.44 r0 top
U16 "TCA9517ADGKR" DGK0008A_N 2859.97,984.44 r0 bottom
VB "5002" Keystone5002 1881.78,2512.5 r0 top
VCC "5000" Keystone5000 2456.4,1097.63 r90 top
VDD "5000" Keystone5000 1149.36,1555.77 r90 top
VLOAD "VOUT" Keystone5000 5377.5,1517.5 r90 top
VOUT "5000" Keystone5000 3448.54,2512.5 r180 top
VSS1 "5001" Keystone5001 1149.36,1392.85 r270 top
VSS2 "5001" Keystone5001 1072.35,1727.16 r90 top

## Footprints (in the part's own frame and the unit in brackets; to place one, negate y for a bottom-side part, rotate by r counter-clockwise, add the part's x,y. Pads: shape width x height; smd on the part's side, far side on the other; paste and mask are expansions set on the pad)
0603 [mm] "0603 from SM-752 data"
  rect 1x0.95 smd: 1(-0.8,0) 2(0.8,0)
  silkscreen extent -1.52,-0.69 1.52,0.69, body extent -0.87,-0.47 0.87,0.47, height 1
0603L [mm] "0603 from SM-752 data"
  rect 0.8x0.85 smd: 1(-0.7,0) 2(0.7,0)
  silkscreen extent -0.07,-0.33 0.07,0.33, body extent -0.87,-0.47 0.87,0.47, height 1
0805_HV [mil] "0805 with 30mil clearance between pads"
  rect 50x63 smd: 1(-40,0) 2(40,0)
  silkscreen extent -74,-40 74,40, body extent -43,-29 43,29, height 57
1206 [mm] "1206 from SM-752 data"
  rect 1.3x1.85 smd: 1(-1.45,0) 2(1.45,0)
  silkscreen extent -2.4,-1.21 2.4,1.21, body extent -1.7,-0.9 1.7,0.9, height 1.35
1206_180 [mm] "1206_180"
  rect 1.1x1.6 smd: 1(-1.7,0) 2(1.7,0)
  silkscreen extent -0.9,-1 0.9,1, body extent -1.75,-0.95 1.75,0.95, height 1.8
1210_270 [mm] "1210"
  rect 1.3x2.7 smd: 1(-1.45,0) 2(1.45,0)
  silkscreen extent -2.32,-1.57 2.32,1.57, body extent -1.7,-1.35 1.7,1.35, height 2.7
1812 [mm]
  rect 1.6x3.4 smd: 1(-2,0) 2(2,0)
  silkscreen extent -0.8,-1.6 0.8,1.6, body extent -2.4,-1.7 2.4,1.7, height 1.35
1812_HV [mil] "PRG recommended land pattern"
  rect 60x140 smd: 1(-85,0) 2(85,0)
  silkscreen extent -129,-84 129,84, body extent -94,-67 94,67, height 53
2512 [mm] "Chip Resistor, Body 6.3x3.2mm, IPC Medium Density"
  rect 1.3x3.4 smd: 1(-2.95,0) 2(2.95,0)
  silkscreen extent -1.9,-1.6 1.9,1.6, body extent -3.22,-1.67 3.22,1.67, height 0.71
Bumpon_SJ5003Transparent [mil] "3M Hemispherical Bumpon transparent"
  round 1 on Mech4: 0(0,0)
  silkscreen extent -228,-228 228,228, body extent -219,-219 219,219, height 197
CAPSMT_62_KE0 [mm] "12.5 x 13.5mm:  Chemi-Con KE0"
  rect 5.7x2.5 smd: 1(-4.85,0) 2(4.85,0)
  silkscreen extent -6.6,-6.6 6.6,6.6, body extent -6.6,-6.6 6.6,6.6, height 14
CONN_2510-6002 [mm] "3M 2500 series TS-0770-L December 15, 2011"
  rect 1.65x1.65 hole 1.016 mask+0: 1(-5.08,-1.27)
  round 1.65 hole 1.016 mask+0: 2(-5.08,1.27) 3(-2.54,-1.27) 4(-2.54,1.27) 5(0,-1.27) 6(0,1.27) 7(2.54,-1.27) 8(2.54,1.27) 9(5.08,-1.27) 10(5.08,1.27)
  silkscreen extent -10.01,-4.17 10.01,4.47, body extent -10.01,-4.11 10.01,4.52, height 9.92
D0008A-MFG [mm]
  rrect17% 1.55x0.6 smd paste+0 mask+0: 1(-2.7,1.905) 2(-2.7,0.635) 3(-2.7,-0.635) 4(-2.7,-1.905) 5(2.7,-1.905) 6(2.7,-0.635) 7(2.7,0.635) 8(2.7,1.905)
  silkscreen extent -4.17,-2.5 1.5,2.5, body extent -3.57,-2.75 3.57,2.75, height 0.25
DBV0005A_M [mm] "SOT23, 5-Leads, Body 2.9x1.6mm, Pitch 0.95mm, Lead Span 2.8mm, IPC Low Density"
  rrect15% 1.2x0.65 smd: 1(-1.475,0.95) 2(-1.475,0) 3(-1.475,-0.95) 4(1.475,-0.95) 5(1.475,0.95)
  silkscreen extent -0.15,-1.55 0.15,1.55, body extent -1.42,-1.46 1.42,1.46, height 1.09
DBV0006A-MFG [mm]
  rrect17% 1.1x0.6 smd paste+0 mask+0: 1(-1.3,0.95) 2(-1.3,0) 3(-1.3,-0.95) 4(1.3,-0.95) 5(1.3,0) 6(1.3,0.95)
  silkscreen extent -2.52,-1.53 0.35,1.53, body extent -1.95,-1.78 1.95,1.78, height 0.25
DBZ0003A_N [mm] "SOT23, 3-Leads, Body 2.9x1.3mm, Pitch 0.95mm, Lead Span 2.4mm, IPC Medium Density"
  rrect17% 1x0.6 smd: 1(-1.2,0.95) 2(-1.2,-0.95) 3(1.2,0)
  silkscreen extent 0.2,-1.5 0.7,1.5, body extent -1.26,-1.46 1.26,1.46, height 0.98
DEM8030C [mm] "SMD, 2-Leads, Body 8x8mm"
  rrect7% 1.5x1.5 smd: 1(-2,0) 2(2,0)
  Top Layer region: 2.5,-4 4,-2.5 4,2.5 2.5,4 0.9,4 0.9,-4
  Top Layer region: -2.5,-4 -4,-2.5 -4,2.5 -2.5,4 -0.9,4 -0.9,-4
  body extent -4,-4 4,4, height 3
DGK0008A_N [mm] "TSOP, 8-Leads, Body 3x3mm, Pitch 0.65mm, IPC Medium Density"
  oval 1.35x0.45 smd: 1(-2.225,0.975) 2(-2.225,0.325) 3(-2.225,-0.325) 4(-2.225,-0.975) 5(2.225,-0.975) 6(2.225,-0.325) 7(2.225,0.325) 8(2.225,0.975)
  silkscreen extent -2.75,-1.55 0.95,1.55, body extent -2.45,-1.5 2.45,1.5, height 0.96
DGS0010A-MFG [mm]
  rrect33% 1.45x0.3 smd paste+0 mask+0: 1(-2.2,1) 2(-2.2,0.5) 3(-2.2,0) 4(-2.2,-0.5) 5(-2.2,-1) 6(2.2,-1) 7(2.2,-0.5) 8(2.2,0) 9(2.2,0.5) 10(2.2,1)
  silkscreen extent -3.6,-1.55 1.05,1.55, body extent -3.03,-1.8 3.03,1.8, height 0.25
DO1608C [mm] "DO1608C"
  rect 1.4x3.56 smd: 1(-2.73,0) 2(2.73,0)
  silkscreen extent -3.3,-2.55 3.3,2.55, body extent -3.27,-2.22 3.33,2.23, height 2.92
DQK0006C [mm] "WSON"
  rrect12% 0.9x0.86 on Top Paste: 0(0,0.325)
  rrect34% 0.7x0.29 on Top Paste: 0(0.095,-0.65)
  rrect33% 0.45x0.3 smd: 1(-0.975,0.65) 2(-0.975,0) 3(-0.975,-0.65) 4(0.975,-0.65) 5(0.975,0) 6(0.975,0.65)
  rrect33% 0.75x0.3 smd paste-0.15: 7(0.095,-0.65)
  rrect11% 1x0.95 smd paste-0.5: 8(0,0.325)
  silkscreen extent -1.15,-1.15 1.15,1.15, body extent -1,-1 1,1, height 0.82
FCC_disclaimer [mil]
FP-750320237_SMT12_29MM65_21MM8-MFG [mm]
  rrect8% 3.05x1.27 smd paste+0 mask+0: 1(-13.26,7.5) 2(-13.26,4.5) 3(-13.26,1.5) 4(-13.26,-1.5) 5(-13.26,-4.5) 6(-13.26,-7.5) 7(13.26,-7.5) 8(13.26,-4.5) 9(13.26,-1.5) 10(13.26,1.5) 11(13.26,4.5) 12(13.26,7.5)
  silkscreen extent -15.47,-10.9 14.82,10.9, body extent -14.92,-11 14.92,11, height 0.25
FP-BAS70-04-E3-18_SOT23-3-MFG [mm]
  rrect14% 0.9x0.7 smd paste+0 mask+0: 1(-1,0.95) 2(-1,-0.95) 3(1,0)
  silkscreen extent -0.71,-1.55 0.71,1.55, body extent -1.55,-1.65 1.55,1.65, height 0.25
FP-C1608X8R1E683M080AA_0603-MFG [mm]
  rrect14% 0.7x0.7 smd paste+0 mask+0: 1(-0.7,0) 2(0.7,0)
  silkscreen extent -0.8,-0.75 0.8,0.75, body extent -1.15,-0.55 1.15,0.55, height 0.25
FP-CM7060P701R-10_SMT_CMC_7MM0_6MM0-MFG [mm]
  rrect7% 2.2x1.5 smd paste+0 mask+0: 1(-2.35,1.5) 2(-2.35,-1.5) 3(2.35,-1.5) 4(2.35,1.5)
  silkscreen extent -4.57,-3.25 3.85,3.25, body extent -3.5,-3 3.5,3, height 3.8
IHLP-2020CZ [mil] "Vishay Dale"
  rrect5% 75.5x110 smd: 1(-80.25,0) 2(80.25,0)
  silkscreen extent -101,-101 101,101, body extent -107,-101 107,101, height 113
IND_PIMB065T [mm] "Cyntec PMB065T-000 Rev A1"
  rect 2.35x3.5 smd: 1(-3.025,0) 2(3.025,0)
  silkscreen extent -3.9,-3.6 3.9,3.6, body extent -3.65,-3.4 3.65,3.4, height 5
Keystone5000 [mil] "For Keystone 500x miniature loop terminals"
  round 80 hole 40: 1(0,0)
  silkscreen extent -52,-52 52,52, body extent -49,-49 49,49, height 182
Keystone5001 [mil] "For Keystone 500x miniature loop terminals"
  round 80 hole 40: 1(0,0)
  silkscreen extent -52,-52 52,52, body extent -49,-49 49,49, height 182
Keystone5002 [mil] "For Keystone 500x miniature loop terminals"
  round 80 hole 40: 1(0,0)
  silkscreen extent -52,-52 52,52, body extent -49,-49 49,49, height 182
Keystone5003 [mil] "For Keystone 500x miniature loop terminals"
  round 80 hole 40: 1(0,0)
  silkscreen extent -52,-52 52,52, body extent -49,-49 49,49, height 182
MLP08S [mm] "Fairchild MLP08S recommended land pattern"
  rect 0.7x0.42 smd mask+0.051: 1(-1.4,0.975) 2(-1.4,0.325) 3(-1.4,-0.325) 4(-1.4,-0.975) 5(1.4,-0.975) 6(1.4,-0.325) 7(1.4,0.325) 8(1.4,0.975)
  Top Layer region: -0.4,-1.185 1.3,-1.185 1.3,1.185 -0.4,1.185
  silkscreen extent -1.8,-1.8 1.8,1.8, body extent -1.67,-1.67 1.67,1.67, height 0.81
N04C [mm] "FAIRCHILD"
  rect 1.3x1.5 smd mask+0.065: 1(-4.587,1.27) 2(-4.612,-1.27) 3(4.588,-1.27) 4(4.613,1.27)
  silkscreen extent -3.56,-2.3 3.56,2.72, body extent -5.08,-2.3 5.08,2.3, height 3.87
Panasonic_G [mm] "SMD, 2-Leads, Dia 10mm"
  rect 4.1x2 smd: 1(-4.35,0) 2(4.35,0)
  silkscreen extent -5.25,-5.25 5.25,5.25, body extent -5.25,-5.25 5.25,5.25, height 10.51
PowerPAK_SO-8_NoVias [mil] "Vishay PowerPAK SO-8, IPC Medium density tweaked to match STEP model"
  rect 50x24 smd mask+2.99: 1(-109.5,75) 2(-109.5,25) 3(-109.5,-25) 4(-109.5,-75)
  rect 48x24 smd mask+2.99: 5(109.5,-75) 8(109.5,75)
  rect 48x24 smd paste-12 mask+2.99: 6(109.5,-25) 7(109.5,25)
  rect 150x154 smd paste-75 mask+2.99: 9(22.5,0)
  silkscreen extent -114,-104 62,113, body extent -121,-102 121,101, height 43
RMT0045A [mm] "VQFN-45"
  rrect50% 0.6x0.2 smd: 1(-2.4,2.6) 2(-2.4,2.2) 3(-2.4,1.8) 4(-2.4,1.4) 5(-2.4,1) 6(-2.4,0.6) 7(-2.4,0.2) 8(-2.4,-0.2) 9(-2.4,-0.6) 10(-2.4,-1.4) 11(-2.4,-1.8) 12(-2.4,-2.2) 13(-2.4,-2.6) 23(2.4,-2.6) 24(2.4,-2.2) 25(2.4,-1.8) 26(2.4,-1.4) 27(2.4,-1) 28(2.4,-0.6) 29(2.4,-0.2) 30(2.4,0.6) 31(2.4,1) 32(2.4,1.4) 33(2.4,1.8) 34(2.4,2.2) 35(2.4,2.6)
  rrect50% 0.2x0.6 smd: 14(-1.8,-3.4) 15(-1.4,-3.4) 16(-1,-3.4) 17(-0.6,-3.4) 18(-0.2,-3.4) 19(0.2,-3.4) 20(0.6,-3.4) 21(1,-3.4) 22(1.4,-3.4) 36(1.8,3.4) 37(1.4,3.4) 38(1,3.4) 39(0.6,3.4) 40(0.2,3.4) 41(-0.2,3.4) 42(-0.6,3.4) 43(-1,3.4) 44(-1.4,3.4) 45(-1.8,3.4)
  rrect5% 3.7x2.1 smd paste-2: 46(0,1.4)
  rrect5% 2.9x2.15 smd paste-2: 47(0,-1.375)
  body extent -2.55,-3.55 2.55,3.55, height 1.01
SMA [mm] "Molded Diode, 2-Leads, Body 4.3x2.6mm, IPC Medium Density, based on OnSemi component dimensions and land pattern"
  rect 2x2 smd: 1(-2,0) 2(2,0)
  silkscreen extent -3.66,-1.57 2.79,1.57, body extent -2.6,-1.3 2.6,1.3, height 2.42
SMC [mil] "Molded Diode, 2-Leads, Body 6.9x5.8mm, IPC Medium Density, based on OnSemi component dimensions and land patterns"
  rect 110x150 smd: 1(-140.49,0) 2(140.49,0)
  silkscreen extent -221,-124 189,123, body extent -156,-116 156,116, height 91
SOD-123 [mm] "On Semi recommended land pattern"
  rect 0.915x1.22 smd: 1(-1.637,0) 2(1.637,0)
  silkscreen extent -2.74,-1.17 2.03,1.17, body extent -1.93,-0.9 1.93,0.9, height 1.35
SOP-4 [mm] "Vishay Half Pitch Mini-Flat Package"
  rect 1.3x0.9 smd: 1(-3.15,0.635) 2(-3.15,-0.635) 3(3.15,-0.635) 4(3.15,0.635)
  silkscreen extent -2.2,-1.41 2.2,1.39, body extent -3.5,-1.4 3.5,1.4, height 2.12
SOT-23 [mm] "SOT23, 3-Leads, Body 2.9x1.3mm, Pitch 0.95mm, Lead Span 2.5mm, IPC Medium Density"
  rrect50% 1x0.6 smd: 1(-1.2,0.95) 2(-1.2,-0.95) 3(1.2,0)
  silkscreen extent -1.62,-1.5 0.7,1.5, body extent -1.16,-1.45 1.21,1.45, height 1
SOT-89-3 [mm] "SOT, 3-Leads, Body 4.6 x 2.6 mm, Pitch 1.5mm"
  rect 1.4x0.9 smd: 1(-1.9,1.5) 3(-1.9,-1.5)
  rect 1.8x0.9 smd: 2(-1.7,0)
  oct 3.4x1.9 smd: 4(0.9,0)
  silkscreen extent -1.3,-2.45 1.33,2.45, body extent -2.42,-2.28 1.83,2.32, height 1.62
TE_5-146278-2 [mm] "TE CONNECTIVITY"
  rect 1.65x1.65 hole 1: 1(-1.27,0)
  round 1.65 hole 1: 2(1.27,0)
  silkscreen extent -2.92,-1.27 2.54,1.27, body extent -2.41,-1.17 2.41,1.17, height 8.13
TE_5-146278-3 [mm] "TE CONNECTIVITY"
  rect 1.65x1.65 hole 1: 1(-2.54,0)
  round 1.65 hole 1: 2(0,0) 3(2.54,0)
  silkscreen extent -4.19,-1.27 3.81,1.27, body extent -3.68,-1.17 3.68,1.17, height 8.13
TEC_1-406541-1 [mm] "TE Connectivity"
  round 1.4 hole 0.89: 1(3.56,-0.18) 2(2.54,1.6) 3(1.52,-0.18) 4(0.5,1.6) 5(-0.52,-0.18) 6(-1.54,1.6) 7(-2.56,-0.18) 8(-3.58,1.6)
  round 2.1 hole 1.57: 9(8.12,0.71) 10(-8.14,0.71)
  round 3.759 hole 3.251: 11(6.34,-2.72) 12(-6.36,-2.72)
  silkscreen extent -9.69,-8 9.69,8.06, body extent -9.33,-8 9.31,7.75, height 14.8
TERM_BLK_ED555-2DS [mil]
  rrect4% 100x100 hole 50: 1(0,0)
  round 100 hole 50: 2(138,0)
  silkscreen extent -93,-161 215,113, body extent -69,-150 207,106, height 323
TRANS_Fairchild_PQFN08A [mm] "Fairchild PQFN08A recommended land pattern"
  rect 1.27x0.61 smd: 1(-2.67,1.905) 2(-2.67,0.635) 3(-2.67,-0.635) 4(-2.67,-1.905) 5(2.67,-1.905) 6(2.67,-0.635) 7(2.67,0.635) 8(2.67,1.905)
  Top Layer region: -1.215,-2.55 2.535,-2.55 2.535,2.55 -1.215,2.55
  silkscreen extent -3.2,-2.7 3.2,2.7, body extent -3.05,-2.55 3.05,2.55, height 1.11
WE-HCB_1890 [mm] "WURTH ELEKTRONIK"
  rect 6x6 smd: 1(-6.65,0) 2(6.65,0)
  silkscreen extent -9.7,-9.4 9.7,9.4, body extent -9.65,-9.35 9.65,9.35, height 9.2
WEEE_Minimum [mil] "WEEElie bin"
  silkscreen extent -95,-172 99,104
WL-SMCW_YELLOW [mm] "WURTH"
  rect 0.8x0.8 smd: 1(-0.8,0) 2(0.8,0)
  silkscreen extent -1.9,-0.8 1.2,0.8, body extent -0.85,-0.45 0.85,0.45, height 0.8
WSLHP0805 [mm] "Vishay"
  rect 1.02x1.27 smd: 1(-0.76,0) 2(0.76,0)
  silkscreen extent -0.6,-0.9 0.6,0.9, body extent -1.14,-0.76 1.14,0.76, height 0.51
Wurth_7490220122 [mm] "SMD, 24-Leads, Body 14.7x18.29mm"
  rect 2.29x0.76 smd: 1(-7.24,6.985) 2(-7.24,5.715) 3(-7.24,4.445) 4(-7.24,3.175) 5(-7.24,1.905) 6(-7.24,0.635) 7(-7.24,-0.635) 8(-7.24,-1.905) 9(-7.24,-3.175) 10(-7.24,-4.445) 11(-7.24,-5.715) 12(-7.24,-6.985) 13(7.24,-6.985) 14(7.24,-5.715) 15(7.24,-4.445) 16(7.24,-3.175) 17(7.24,-1.905) 18(7.24,-0.635) 19(7.24,0.635) 20(7.24,1.905) 21(7.24,3.175) 22(7.24,4.445) 23(7.24,5.715) 24(7.24,6.985)
  silkscreen extent -7.7,-9.15 7.35,9.15, body extent -7.35,-9.15 7.35,9.15, height 8.81
Wurth_60900213421 [mil] "Shunt, 2.54mm, Black"
  round 1 on Mech3: 0(0,0)
  body extent -98,-48 98,48, height 338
